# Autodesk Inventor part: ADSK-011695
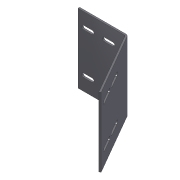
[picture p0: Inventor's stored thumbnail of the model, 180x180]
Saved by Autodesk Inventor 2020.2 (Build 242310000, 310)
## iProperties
Created: 2000-03
Part Number: ADSK-011695
Document SubType Name: Modeling
Designer: sspink
Material: Pearson CRS
Density: 1 g/cm^3
Sheet Metal Rule: Stahlblech 1.0312 - DC05 -   3.0 mm
Appearance: Metal-Steel(Polish)
Mass: 83.0781 g
Surface Area: 590.363 cm^2
Volume: 83.0781 cm^3
Flat Pattern Width: 12.7 cm
Flat Pattern Length: 22.9328 cm
Flat Pattern Area: 291.246 cm^2
Sheet Metal Width: 127,000 mm
Sheet Metal Length: 229,328 mm
Sheet Metal Area: 29124,623 mm^2
Control State: 0
Master: False
Checked Out: False
Shininess: 60.0
Length Units: 11269
Angle Units: 11279
Time Units: 11290
Mass Units: 11283
Length Display Precision: 3
Angle Display Precision: 2
Compacted: True
Cutlength: 704 SI (20.25 X 34.75)
Material Desc: SHEET,HRS,11 GA
Material_Number: Axxxxxx
Dimensions: 127x125,7x160 mm
Mass: 0,083 kg
G_L: 127x229,3 mm
Thickness: 3,000 mm
Semi finished: Stahlblech 1.0312 - DC05 -   3.0 mm
VLT_Material: 1.0312 DC05
Density: 0.0
Volumn: 0.0
Area: 0.0
PropertySet Name: Model Information
Author: sspink
Revision Number: -
Title: ADSK-011695
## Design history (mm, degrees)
node "Face1"
  sketch "Sketch1"
    geometry: L1 (-45, -63.5)-(45, -63.5); L2 (45, -63.5)-(45, 63.5); L3 (45, 63.5)-(-45, 63.5); L4 (-45, 63.5)-(-45, -63.5); 3 further points
    constraints: 8 end point, 2 midpoint, 2 parallel, 1 horizontal, 1 horizontal alignment, 1 perpendicular, 1 vertical alignment
    dimensions: "d0" = 127 distance between parallel lines of L1 L3; "d1" = 90 distance between parallel lines of L2 L4
node "Flange1"
  node "Bend1" dims "d3" = 140, "d4" = 60 deg, "d5" = 3 (= BendRadius), "d32" = 3 (= BendReliefWidth), "d33" = 1.5 (= BendReliefDepth), "d34" = 6 (= MinimumRemnant), "d35" = 3 (= Thickness), "d36" = 3 (= TransitionRadius), "SeamGap" = 0.00508
node "Cut1" dims "d10" = 3 (= Thickness), "d11" = 0
  sketch "Sketch3"
    geometry: L1 (0, 0)-(0, 127) reference; L2 (64, 105)-(48, 105); L3 (48, 105)-(48, 98); L4 (48, 98)-(64, 98); L5 (64, 98)-(64, 105); L6 (48, 101.5)-(64, 101.5); L7 (18, 25.5)-(56, 25.5); L8 (56, 25.5)-(56, 101.5); L9 (56, 101.5)-(18, 101.5); L10 (18, 101.5)-(18, 25.5); L11 (64, 29)-(48, 29); L12 (48, 29)-(48, 22); L13 (48, 22)-(64, 22); L14 (64, 22)-(64, 29); L15 (48, 25.5)-(64, 25.5); L16 (26, 29)-(10, 29); L17 (10, 29)-(10, 22); L18 (10, 22)-(26, 22); L19 (26, 22)-(26, 29); L20 (10, 25.5)-(26, 25.5); L21 (26, 105)-(10, 105); L22 (10, 105)-(10, 98); L23 (10, 98)-(26, 98); L24 (26, 98)-(26, 105); L25 (10, 101.5)-(26, 101.5); A1 r 3.5 centre (64, 101.5) between (64, 98) and (64, 105); A2 r 3.5 centre (48, 101.5) between (48, 105) and (48, 98); A3 r 3.5 centre (64, 25.5) between (64, 22) and (64, 29); A4 r 3.5 centre (48, 25.5) between (48, 29) and (48, 22); A5 r 3.5 centre (26, 25.5) between (26, 22) and (26, 29); A6 r 3.5 centre (10, 25.5) between (10, 29) and (10, 22); A7 r 3.5 centre (26, 101.5) between (26, 98) and (26, 105); A8 r 3.5 centre (10, 101.5) between (10, 105) and (10, 98); 2 further points
    constraints: 48 end point, 16 point on circle, 10 parallel, 9 horizontal, 8 centre point, 8 tangent, 6 midpoint, 5 perpendicular, 1 horizontal alignment
    dimensions: "d6" = 7 distance between parallel lines of L4 L2; "d7" = 16 distance between parallel lines of L5 L3; "d37" = 76 distance of L7.end L8.end; "d38" = 38 distance of L7.start L7.end; "d39" = 18 distance between parallel lines of L1 L10; "d40" = 7 distance between parallel lines of L13 L11; "d41" = 16 distance between parallel lines of L14 L12; "d42" = 7 distance between parallel lines of L18 L16; "d43" = 16 distance between parallel lines of L19 L17; "d44" = 7 distance between parallel lines of L23 L21; "d45" = 16 distance between parallel lines of L24 L22
node "Cut2" dims "d24" = 3 (= Thickness), "d25" = 0
  sketch "Sketch4"
    geometry: L1 (0, 0)-(0, 127) reference; L2 (16, 22)-(41, 22); L3 (41, 22)-(41, 29); L4 (41, 29)-(16, 29); L5 (16, 29)-(16, 22); L6 (16, 25.5)-(41, 25.5); L7 (66.5, 101.5)-(28.5, 101.5); L8 (28.5, 101.5)-(28.5, 25.5); L9 (28.5, 25.5)-(66.5, 25.5); L10 (66.5, 25.5)-(66.5, 101.5); L11 (41, 105)-(16, 105); L12 (16, 101.5)-(41, 101.5); L13 (16, 98)-(41, 98); L14 (41, 98)-(41, 105); L15 (16, 105)-(16, 98); L16 (79, 29)-(54, 29); L17 (54, 25.5)-(79, 25.5); L18 (54, 22)-(79, 22); L19 (79, 22)-(79, 29); L20 (54, 29)-(54, 22); L21 (79, 105)-(54, 105); L22 (54, 101.5)-(79, 101.5); L23 (54, 98)-(79, 98); L24 (79, 98)-(79, 105); L25 (54, 105)-(54, 98); A1 r 3.5 centre (16, 25.5) between (16, 29) and (16, 22); A2 r 3.5 centre (41, 25.5) between (41, 22) and (41, 29); A3 r 3.5 centre (16, 101.5) between (16, 105) and (16, 98); A4 r 3.5 centre (41, 101.5) between (41, 98) and (41, 105); A5 r 3.5 centre (54, 25.5) between (54, 29) and (54, 22); A6 r 3.5 centre (79, 25.5) between (79, 22) and (79, 29); A7 r 3.5 centre (54, 101.5) between (54, 105) and (54, 98); A8 r 3.5 centre (79, 101.5) between (79, 98) and (79, 105); 2 further points
    constraints: 48 end point, 16 point on circle, 10 parallel, 9 horizontal, 8 centre point, 8 tangent, 6 midpoint, 5 perpendicular, 1 horizontal alignment
    dimensions: "d21" = 7 distance between parallel lines of L4 L2; "d46" = 76 distance of L7.end L8.end; "d47" = 28.5 distance between parallel lines of L1 L8; "d48" = 38 distance of L7.start L7.end; "d49" = 25 distance of L6.start L6.end; "d50" = 7 distance between parallel lines of L11 L13; "d51" = 25 distance of L12.start L12.end; "d52" = 7 distance between parallel lines of L16 L18; "d53" = 25 distance of L17.start L17.end; "d54" = 7 distance between parallel lines of L21 L23; "d55" = 25 distance of L22.start L22.end
workplane "Arbeitsebene5"
workplane "Arbeitsebene6"
workpoint "Arbeitspunkt1"
workpoint "Arbeitspunkt2"
workpoint "Arbeitspunkt3"
workpoint "Arbeitspunkt4"
workaxis "Arbeitsachse3"
workaxis "Arbeitsachse4"
workaxis "Arbeitsachse5"
workaxis "Arbeitsachse6"
node "Solide1"
node "Corps solides"
node "Corps surfaciques"
node "Plate1" dims "d35" = 3 (= Thickness)
sketch "Sketch2"
  geometry: L1 (127, 0)-(127, 140); L2 (127, 140)-(0, 140); 1 other entity
  constraints: 4 end point, 4 other
node "Plate2" dims "d3" = 140, "d4" = 60 deg, "d5" = 3 (= BendRadius), "d32" = 3 (= BendReliefWidth), "d33" = 1.5 (= BendReliefDepth), "d34" = 6 (= MinimumRemnant), "d35" = 3 (= Thickness), "d36" = 3 (= TransitionRadius), "SeamGap" = 0.00508
feature "Definition1"
other parameters: "Thickness" = 3 (derived), "BendRadius" = 3 (= Thickness), "BendReliefWidth" = 3 (= Thickness), "BendReliefDepth" = 1.5 (= 0.5 x Thickness), "CornerReliefSize" = 12 (= 4 x Thickness), "MinimumRemnant" = 6 (= 2 x Thickness), "d2" = 3 (= BendRadius), "TransitionRadius" = 3 (= BendRadius), "TailleRayonJacobi" = 3 (= BendRadius), "TailleJeu" = 3 (= Thickness), "KFaktor" = 4.4, "BendRadius" = 3, "BendReliefDepth" = 1.5, "BendReliefWidth" = 3, "CornerReliefSize" = 12, "MinimumRemnant" = 6, "TailleJeu" = 3, "TailleRayonJacobi" = 3, "Thickness" = 3, "TransitionRadius" = 3
